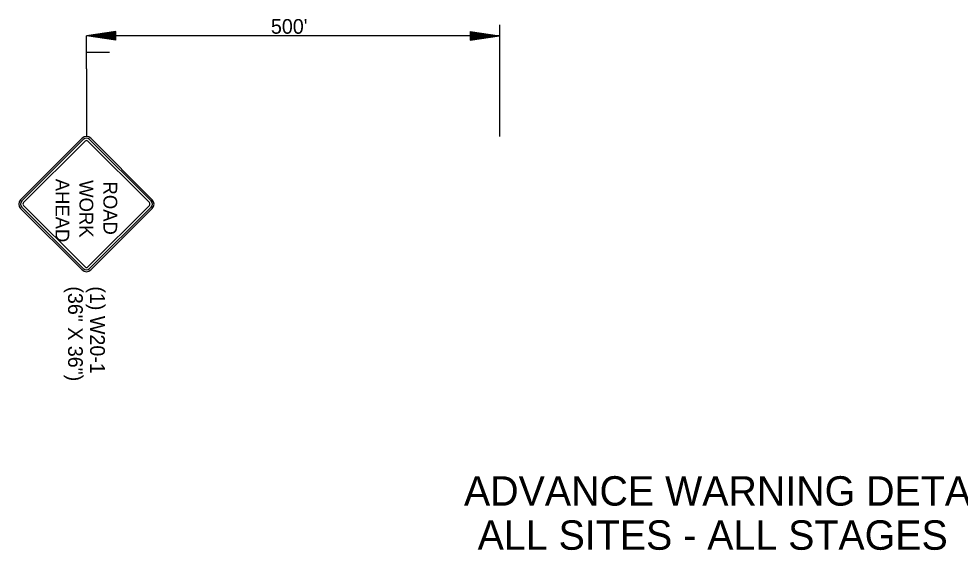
# Model space of a CAD drawing. Extents: x 913 to 1207, y 319 to 519.
# Drawn here: x 994.9 to 1071.7, y 368.7 to 412.1 of the extents above; entities that cross this region are included whole.
import ezdxf

# ---------------------------------------------------------------- set-up
doc = ezdxf.new("R2010")
doc.units = 0
doc.layers.add('R_Annotation', color=7, linetype='Continuous')
doc.layers.add('R_Draft', color=7, linetype='Continuous')

msp = doc.modelspace()

# ---------------------------------------------------------------- linework, layer by layer
at = {"layer": 'R_Annotation'}
for p, q in [((995.048, 397.328), (1000.06, 402.34)), ((995.148, 397.229), (1000.159, 402.241)), ((995.287, 397.09), (1000.298, 402.101)), ((1000.537, 402.101), (1005.549, 397.09)), ((1000.676, 402.241), (1005.688, 397.229)), ((1000.776, 402.34), (1005.787, 397.328)), ((1000.06, 391.601), (995.048, 396.612)), ((1000.159, 391.7), (995.148, 396.712)), ((1000.298, 391.839), (995.287, 396.851)), ((1005.549, 396.851), (1000.537, 391.839)), ((1005.688, 396.712), (1000.676, 391.7)), ((1005.787, 396.612), (1000.776, 391.601))]:
    msp.add_line(p, q, dxfattribs=at)
for centre, radius, start, end in [((1000.418, 401.982), 0.506, 45, 135), ((1000.418, 401.982), 0.366, 45, 135), ((1000.418, 401.982), 0.169, 45, 135), ((995.406, 396.97), 0.506, 135, 225), ((995.406, 396.97), 0.366, 135, 225), ((995.406, 396.97), 0.169, 135, 225), ((1005.429, 396.97), 0.169, 315, 45), ((1005.429, 396.97), 0.366, 315, 45), ((1005.429, 396.97), 0.506, 315, 45), ((1000.418, 391.959), 0.366, 225, 315), ((1000.418, 391.959), 0.169, 225, 315), ((1000.418, 391.959), 0.506, 225, 315)]:
    msp.add_arc(centre, radius, start, end, dxfattribs=at)
at = {"layer": 'R_Draft'}
for p, q in [((1034.123, 411.602), (1034.123, 402.488)), ((1002.81, 411.062), (1000.416, 410.703)), ((1002.81, 411.002), (1000.816, 410.703)), ((1002.81, 410.941), (1001.227, 410.703)), ((1002.81, 410.881), (1001.625, 410.703)), ((1002.81, 410.344), (1002.81, 411.062)), ((1031.729, 411.062), (1034.123, 410.703)), ((1031.729, 411.062), (1031.729, 410.344)), ((1031.729, 411.002), (1033.723, 410.703)), ((1031.729, 410.941), (1033.311, 410.703)), ((1031.729, 410.881), (1032.912, 410.703)), ((1034.123, 410.703), (1000.416, 410.703)), ((1002.81, 410.344), (1000.416, 410.703)), ((1000.418, 408.01), (1000.418, 410.703)), ((1002.81, 410.404), (1000.816, 410.703)), ((1002.81, 410.464), (1001.227, 410.703)), ((1002.81, 410.524), (1001.625, 410.703)), ((1002.81, 410.82), (1002.032, 410.703)), ((1002.81, 410.587), (1002.032, 410.703)), ((1002.81, 410.759), (1002.432, 410.703)), ((1002.81, 410.647), (1002.432, 410.703)), ((1031.729, 410.819), (1032.507, 410.703)), ((1031.729, 410.759), (1032.107, 410.703)), ((1031.729, 410.344), (1034.123, 410.703)), ((1031.729, 410.586), (1032.507, 410.703)), ((1031.729, 410.464), (1033.311, 410.703)), ((1031.729, 410.404), (1033.723, 410.703)), ((1031.729, 410.524), (1032.912, 410.703)), ((1031.729, 410.647), (1032.107, 410.703)), ((1000.457, 409.35), (1002.295, 409.35)), ((1000.418, 408.01), (1000.418, 402.488))]:
    msp.add_line(p, q, dxfattribs=at)

# ---------------------------------------------------------------- texts
at = {"layer": 'R_Annotation'}
for s, height, rotation, p in [(' AHEAD ', 1.125, 270, (997.893, 399.452)), ('WORK', 1.125, 270, (999.846, 398.919)), (' ROAD ', 1.125, 270, (1001.8, 399.224)), ('(36" X 36")', 1.2, 270, (998.918, 390.254)), ('(1) W20-1', 1.2, 270, (1000.718, 390.254)), ('ADVANCE WARNING DETAILS', 2.4, 360, (1031.213, 372.363)), ('ALL SITES - ALL STAGES', 2.4, 360, (1032.328, 368.763))]:
    msp.add_text(s, height=height, rotation=rotation, dxfattribs=at).set_placement(p)
at = {"layer": 'R_Draft'}
msp.add_text("500'", height=1.2, rotation=360, dxfattribs=at).set_placement((1015.465, 410.866))

doc.saveas('drawing.dxf')
